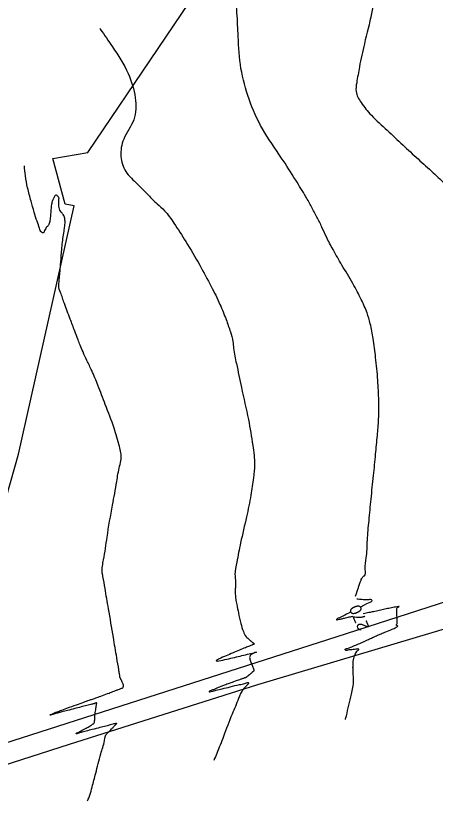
# Model space of a CAD drawing. Extents: x -478464 to -472469, y -1118040 to -1113785.
# Drawn here: x -478027.6 to -477884.4, y -1117519.9 to -1117251.2 of the extents above; entities that cross this region are included whole.
import ezdxf

# ---------------------------------------------------------------- set-up
doc = ezdxf.new("R2010")
doc.units = 0
for name, color, linetype in [('ObPÚ', 7, 'Continuous'), ('silnice', 7, 'Continuous'), ('Vrstevnice_hlavni', 7, 'Continuous'), ('Vrstevnice_popis', 7, 'Continuous'), ('Vrstevnice_vedlejsi', 7, 'Continuous')]:
    doc.layers.add(name, color=color, linetype=linetype)

msp = doc.modelspace()

# ---------------------------------------------------------------- linework, layer by layer
at = {"layer": 'ObPÚ'}
for points in [[(-478036.665, -1117435.774), (-478026.64, -1117400.81), (-478007.71, -1117316.06), (-478010.688, -1117315.457), (-478014.916, -1117299.841), (-478003.02, -1117297.83), (-477955.02, -1117226.727), (-477932.94, -1117194.02), (-477930.86, -1117190.98), (-477927.765, -1117186.164), (-477902.42, -1117146.73), (-477898.94, -1117138.46), (-477889.78, -1117115.18), (-477874.35, -1117091.12), (-477871.53, -1117086.61), (-477868.88, -1117081.98), (-477862.66, -1117057.28), (-477855.79, -1117029.92), (-477851.66, -1117013.57), (-477838.11, -1116918.83), (-477838.17, -1116915.03), (-477838.53, -1116880.06), (-477835.42, -1116846.57)], [(-477192.43, -1117425.62), (-477239.17, -1117423.45), (-477286.2, -1117422.09), (-477330.75, -1117420.42), (-477373.93, -1117418.61), (-477420.9, -1117417.49), (-477422.1, -1117417.56), (-477424.2, -1117417.6), (-477428.82, -1117417.33), (-477494.83, -1117414.18), (-477554.51, -1117411.78), (-477621.5, -1117408.68), (-477644.72, -1117408.28), (-477682.13, -1117413.46), (-477685.93, -1117414.02), (-477688.8, -1117414.36), (-477691.73, -1117414.77), (-477738.55, -1117419.44), (-477782.49, -1117430.5), (-477808.98, -1117437.26), (-477845.5, -1117449.81), (-477945.12, -1117479.46), (-478009.37, -1117499.81), (-478071.71, -1117519.91)]]:
    msp.add_lwpolyline(points, dxfattribs=at)
at = {"layer": 'silnice'}
msp.add_lwpolyline([(-478068.596, -1117511.329), (-477917.95, -1117462.993), (-477779.219, -1117418.245), (-477732.944, -1117407.585), (-477720.808, -1117405.048), (-477704.588, -1117403.835), (-477689.402, -1117401.926), (-477652.852, -1117401.691), (-477590.784, -1117403.37), (-477332.447, -1117414.279), (-477204.956, -1117416.797), (-477142.049, -1117416.797), (-477096.756, -1117410.083), (-477036.34, -1117397.174), (-476978.492, -1117379.033), (-476883.712, -1117344.626), (-476756.221, -1117298.47), (-476633.763, -1117254.832), (-476588.47, -1117242.245), (-476550.726, -1117234.692), (-476503.755, -1117230.496), (-476424.073, -1117228.817), (-476282.324, -1117220.425)], dxfattribs=at)
at = {"layer": 'Vrstevnice_hlavni'}
for points in [[(-477911.583, -1117449.228), (-477910.477, -1117445.772), (-477910.019, -1117444.447), (-477909.658, -1117443.526), (-477909.392, -1117443.009), (-477909.13, -1117442.624), (-477908.873, -1117442.372), (-477908.621, -1117442.252), (-477908.32, -1117440.177), (-477907.97, -1117436.148), (-477907.573, -1117430.164), (-477907.024, -1117423.487), (-477906.324, -1117416.119), (-477905.473, -1117408.06), (-477904.757, -1117400.83), (-477904.178, -1117394.43), (-477903.734, -1117388.86), (-477903.684, -1117382.559), (-477904.026, -1117375.527), (-477904.762, -1117367.764), (-477905.619, -1117361.343), (-477906.598, -1117356.266), (-477907.698, -1117352.532), (-477909.68, -1117347.951), (-477912.544, -1117342.521), (-477916.289, -1117336.243), (-477919.3, -1117330.94), (-477921.576, -1117326.612), (-477923.119, -1117323.257), (-477924.801, -1117319.855), (-477926.621, -1117316.406), (-477928.579, -1117312.91), (-477932.023, -1117307.311), (-477936.953, -1117299.609), (-477943.367, -1117289.805), (-477947.957, -1117279.645), (-477950.723, -1117269.132), (-477951.664, -1117258.263), (-477952.088, -1117250.196), (-477951.996, -1117244.93), (-477951.386, -1117242.465), (-477951.356, -1117240.437), (-477951.906, -1117238.846), (-477954.163, -1117236.539)], [(-477909.977, -1117452.965), (-477906.683, -1117451.282), (-477905.981, -1117450.731), (-477906.225, -1117450.469), (-477907.414, -1117450.497), (-477908.49, -1117450.482), (-477909.453, -1117450.426), (-477911.153, -1117450.228)], [(-477915.078, -1117491.334), (-477914.758, -1117490.096), (-477913.057, -1117482.71), (-477912.276, -1117478.035), (-477912.416, -1117476.071), (-477912.486, -1117474.339), (-477912.485, -1117472.841), (-477912.413, -1117471.575), (-477912.24, -1117470.477), (-477911.965, -1117469.547), (-477911.588, -1117468.784), (-477911.224, -1117468.179), (-477910.875, -1117467.731), (-477910.539, -1117467.441), (-477910.602, -1117467.288), (-477911.064, -1117467.272), (-477911.925, -1117467.394), (-477912.881, -1117467.505), (-477913.932, -1117467.605), (-477915.078, -1117467.696), (-477915.213, -1117467.508), (-477914.336, -1117467.043), (-477912.448, -1117466.301), (-477910.623, -1117465.544), (-477908.86, -1117464.773), (-477907.159, -1117463.989), (-477905.794, -1117463.361), (-477904.767, -1117462.89), (-477904.076, -1117462.575), (-477902.898, -1117462.073), (-477901.234, -1117461.381), (-477899.083, -1117460.501), (-477897.749, -1117459.856), (-477897.231, -1117459.445), (-477897.531, -1117459.27), (-477897.673, -1117459.108), (-477897.657, -1117458.96), (-477897.483, -1117458.826), (-477897.4, -1117458.217), (-477897.409, -1117457.134), (-477897.509, -1117455.576), (-477897.559, -1117454.436), (-477897.557, -1117453.715), (-477897.505, -1117453.413), (-477897.342, -1117453.155), (-477897.069, -1117452.941), (-477896.686, -1117452.773), (-477897.009, -1117452.778), (-477898.037, -1117452.957), (-477899.772, -1117453.31), (-477901.6, -1117453.691), (-477903.52, -1117454.102), (-477905.533, -1117454.541), (-477907.034, -1117454.867), (-477908.024, -1117455.082), (-477908.98, -1117455.286)], [(-477913.191, -1117454.606), (-477915.268, -1117455.667), (-477916.239, -1117456.168), (-477917.145, -1117456.64), (-477917.983, -1117457.083), (-477918.11, -1117457.279), (-477917.524, -1117457.226), (-477916.227, -1117456.926), (-477915.1, -1117456.663), (-477914.142, -1117456.438), (-477912.565, -1117456.061)]]:
    msp.add_spline(points, degree=3, dxfattribs=at)
at = {"layer": 'Vrstevnice_vedlejsi'}
for points in [[(-477804.386, -1117419.488), (-477804.459, -1117419.188), (-477804.433, -1117418.828), (-477804.309, -1117418.408), (-477804.087, -1117417.929), (-477803.934, -1117417.608), (-477803.851, -1117417.446), (-477803.837, -1117417.442), (-477803.822, -1117417.43), (-477803.805, -1117417.41), (-477803.787, -1117417.381), (-477803.78, -1117417.35), (-477803.784, -1117417.318), (-477803.798, -1117417.285), (-477803.846, -1117417.041), (-477803.927, -1117416.587), (-477804.04, -1117415.924), (-477804.155, -1117415.491), (-477804.272, -1117415.29), (-477804.39, -1117415.321), (-477804.727, -1117415.276), (-477805.285, -1117415.155), (-477806.062, -1117414.959), (-477806.661, -1117414.179), (-477807.083, -1117412.816), (-477807.326, -1117410.868), (-477807.929, -1117408.579), (-477808.891, -1117405.947), (-477810.211, -1117402.974), (-477810.939, -1117399.862), (-477811.074, -1117396.614), (-477810.616, -1117393.228), (-477810.756, -1117387.654), (-477811.492, -1117379.894), (-477812.825, -1117369.947), (-477814.001, -1117361.455), (-477815.021, -1117354.417), (-477815.885, -1117348.835), (-477817.217, -1117342.529), (-477819.02, -1117335.501), (-477821.291, -1117327.751), (-477824.632, -1117319.053), (-477829.042, -1117309.407), (-477834.521, -1117298.815), (-477839.072, -1117290.84), (-477842.696, -1117285.481), (-477845.392, -1117282.741), (-477847.121, -1117280.083), (-477847.883, -1117277.508), (-477847.679, -1117275.017), (-477848.818, -1117269.742), (-477851.301, -1117261.684), (-477855.128, -1117250.842), (-477858.13, -1117241.057), (-477860.308, -1117232.328), (-477861.662, -1117224.656), (-477862.366, -1117217.654), (-477862.42, -1117211.323), (-477861.824, -1117205.661), (-477863.512, -1117199.828), (-477867.485, -1117193.824), (-477873.743, -1117187.648), (-477879.164, -1117182.394), (-477883.749, -1117178.064), (-477887.498, -1117174.655), (-477893.02, -1117171.134), (-477900.315, -1117167.498), (-477909.382, -1117163.749), (-477915.572, -1117161.214), (-477918.886, -1117159.892), (-477919.321, -1117159.784), (-477919.639, -1117159.708), (-477919.838, -1117159.664), (-477919.919, -1117159.653), (-477920.013, -1117159.646), (-477920.119, -1117159.642), (-477920.238, -1117159.643), (-477924.722, -1117159.296), (-477933.571, -1117158.602), (-477934.082, -1117158.562)], [(-477954.454, -1117189.777), (-477948.211, -1117191.791), (-477936.422, -1117195.896), (-477928.048, -1117199.17), (-477923.089, -1117201.613), (-477921.545, -1117203.226), (-477918.986, -1117206.68), (-477915.414, -1117211.974), (-477910.828, -1117219.108), (-477907.487, -1117225.392), (-477905.391, -1117230.828), (-477904.539, -1117235.414), (-477904.79, -1117241.921), (-477906.143, -1117250.35), (-477908.597, -1117260.701), (-477910.296, -1117268.595), (-477911.24, -1117274.034), (-477911.429, -1117277.017), (-477909.757, -1117280.714), (-477906.224, -1117285.125), (-477900.83, -1117290.251), (-477895.519, -1117295.224), (-477890.29, -1117300.046), (-477885.145, -1117304.716), (-477880.549, -1117309.008), (-477876.503, -1117312.924), (-477873.006, -1117316.462), (-477870.428, -1117320.233), (-477868.77, -1117324.236), (-477868.031, -1117328.472), (-477866.681, -1117334.328), (-477864.72, -1117341.805), (-477862.147, -1117350.902), (-477860.639, -1117359.029), (-477860.198, -1117366.184), (-477860.823, -1117372.368), (-477861.454, -1117378.874), (-477862.091, -1117385.702), (-477862.734, -1117392.851), (-477863.037, -1117399.446), (-477862.998, -1117405.488), (-477862.617, -1117410.976), (-477862.345, -1117415.865), (-477862.18, -1117420.156), (-477862.122, -1117423.848), (-477862.019, -1117426.978), (-477861.868, -1117429.545), (-477861.672, -1117431.549), (-477861.33, -1117433.074), (-477860.844, -1117434.119), (-477860.213, -1117434.684), (-477859.737, -1117435.119), (-477859.415, -1117435.425), (-477859.249, -1117435.601), (-477859.805, -1117436.002), (-477861.085, -1117436.629), (-477863.088, -1117437.481), (-477864.741, -1117438.177), (-477866.043, -1117438.717), (-477866.996, -1117439.1), (-477868.438, -1117439.714), (-477870.371, -1117440.557), (-477872.793, -1117441.629), (-477874.666, -1117442.446), (-477875.99, -1117443.008), (-477876.763, -1117443.314), (-477877.55, -1117443.633), (-477878.351, -1117443.965), (-477879.164, -1117444.31), (-477879.357, -1117444.451), (-477878.928, -1117444.387), (-477877.878, -1117444.12), (-477877.052, -1117443.907), (-477876.449, -1117443.747), (-477876.07, -1117443.642), (-477874.783, -1117443.296), (-477872.588, -1117442.71)], [(-477998.879, -1117255.557), (-477998.727, -1117255.77), (-477994.613, -1117261.766), (-477989.226, -1117270.883), (-477986.788, -1117279.171), (-477987.299, -1117286.631), (-477990.759, -1117293.261), (-477991.682, -1117299.15), (-477990.068, -1117304.296), (-477985.915, -1117308.701), (-477982.328, -1117312.403), (-477979.306, -1117315.404), (-477976.849, -1117317.702), (-477973.612, -1117321.957), (-477969.594, -1117328.168), (-477964.797, -1117336.336), (-477960.899, -1117343.504), (-477957.9, -1117349.67), (-477955.8, -1117354.835), (-477954.323, -1117359.055), (-477953.469, -1117362.331), (-477953.239, -1117364.661), (-477952.282, -1117369.883), (-477950.598, -1117377.995), (-477948.188, -1117388.997), (-477946.693, -1117397.801), (-477946.113, -1117404.405), (-477946.449, -1117408.81), (-477947.352, -1117414.723), (-477948.823, -1117422.144), (-477950.861, -1117431.072), (-477952.177, -1117437.645), (-477952.771, -1117441.863), (-477952.644, -1117443.726), (-477952.589, -1117445.223), (-477952.606, -1117446.354), (-477952.696, -1117447.119), (-477952.711, -1117448.007), (-477952.649, -1117449.018), (-477952.512, -1117450.153), (-477952.156, -1117452.114), (-477951.583, -1117454.901), (-477950.791, -1117458.515), (-477949.91, -1117461.246), (-477948.939, -1117463.094), (-477947.878, -1117464.059), (-477947.136, -1117464.728), (-477946.712, -1117465.101), (-477946.606, -1117465.179), (-477946.495, -1117465.26), (-477946.379, -1117465.346), (-477946.257, -1117465.436), (-477946.233, -1117465.524), (-477946.307, -1117465.609), (-477946.478, -1117465.691), (-477946.651, -1117465.772), (-477946.824, -1117465.851), (-477946.999, -1117465.928), (-477947.792, -1117466.25), (-477949.203, -1117466.816), (-477951.232, -1117467.627), (-477953.439, -1117468.556), (-477955.824, -1117469.604), (-477958.387, -1117470.771), (-477959.194, -1117471.349), (-477958.243, -1117471.339)], [(-477991.867, -1117477.245), (-477991.928, -1117477.172), (-477992.04, -1117476.677), (-477992.202, -1117475.763), (-477992.413, -1117474.428), (-477993.107, -1117470.277), (-477994.282, -1117463.311), (-477995.94, -1117453.528), (-477997.123, -1117446.591), (-477997.83, -1117442.497), (-477998.062, -1117441.249), (-477997.593, -1117436.785), (-477996.423, -1117429.106), (-477994.553, -1117418.212), (-477993.126, -1117410.136), (-477992.143, -1117404.879), (-477991.604, -1117402.439), (-477992.237, -1117398.118), (-477994.043, -1117391.915), (-477997.021, -1117383.831), (-477999.558, -1117377.283), (-478001.654, -1117372.273), (-478003.307, -1117368.799), (-478004.636, -1117365.887), (-478005.64, -1117363.535), (-478006.319, -1117361.745), (-478007.439, -1117358.786), (-478009, -1117354.657), (-478011.003, -1117349.359), (-478012.316, -1117345.574), (-478012.939, -1117343.304), (-478012.872, -1117342.547), (-478012.777, -1117341.561), (-478012.655, -1117340.344), (-478012.505, -1117338.897), (-478012.348, -1117337.07), (-478012.182, -1117334.863), (-478012.009, -1117332.276), (-478011.775, -1117329.718), (-478011.478, -1117327.189), (-478011.12, -1117324.688), (-478010.876, -1117322.931), (-478010.745, -1117321.917), (-478010.728, -1117321.646), (-478010.753, -1117321.243), (-478010.821, -1117320.708), (-478010.93, -1117320.041), (-478011.029, -1117319.606), (-478011.115, -1117319.402), (-478011.19, -1117319.431), (-478011.241, -1117319.41), (-478011.268, -1117319.341), (-478011.271, -1117319.224), (-478011.447, -1117318.941), (-478011.795, -1117318.493), (-478012.316, -1117317.879), (-478012.672, -1117317.097), (-478012.863, -1117316.147), (-478012.89, -1117315.028), (-478012.892, -1117314.215), (-478012.869, -1117313.71), (-478012.821, -1117313.512), (-478012.909, -1117313.243), (-478013.131, -1117312.902), (-478013.489, -1117312.491), (-478013.809, -1117312.342), (-478014.093, -1117312.455), (-478014.34, -1117312.83), (-478014.581, -1117313.247), (-478014.817, -1117313.705), (-478015.046, -1117314.206), (-478015.238, -1117314.822), (-478015.392, -1117315.554), (-478015.508, -1117316.401), (-478015.602, -1117317.301), (-478015.672, -1117318.253), (-478015.72, -1117319.257), (-478015.808, -1117320.173), (-478015.935, -1117321.003), (-478016.103, -1117321.746), (-478016.33, -1117322.362), (-478016.618, -1117322.853), (-478016.967, -1117323.218), (-478017.343, -1117323.742), (-478017.748, -1117324.426), (-478018.182, -1117325.269), (-478018.755, -1117325.029), (-478019.468, -1117323.706), (-478020.32, -1117321.3), (-478021.282, -1117318.195), (-478022.355, -1117314.389), (-478023.538, -1117309.884), (-478024.297, -1117305.737), (-478024.625, -1117302.334)], [(-477958.243, -1117471.339), (-477955.536, -1117470.741), (-477952.915, -1117470.142), (-477950.378, -1117469.541), (-477947.927, -1117468.939), (-477946.283, -1117468.538), (-477945.445, -1117468.338), (-477945.414, -1117468.339), (-477945.712, -1117468.473), (-477946.339, -1117468.742), (-477947.296, -1117469.144), (-477947.728, -1117469.923), (-477947.635, -1117471.079), (-477947.017, -1117472.611), (-477946.597, -1117473.709), (-477946.375, -1117474.371), (-477946.35, -1117474.598), (-477946.374, -1117474.773), (-477946.445, -1117474.897), (-477946.564, -1117474.97), (-477946.676, -1117475.037), (-477946.782, -1117475.1), (-477946.881, -1117475.157), (-477946.943, -1117475.205), (-477946.968, -1117475.243), (-477946.957, -1117475.27), (-477947.157, -1117475.466), (-477947.57, -1117475.831), (-477948.194, -1117476.365), (-477948.672, -1117476.747), (-477949.004, -1117476.976), (-477949.191, -1117477.054), (-477949.465, -1117477.156), (-477949.826, -1117477.283), (-477950.274, -1117477.435), (-477951.24, -1117477.772), (-477952.723, -1117478.294), (-477954.724, -1117479.003), (-477956.35, -1117479.597), (-477957.602, -1117480.076), (-477958.479, -1117480.441), (-477959.413, -1117480.834), (-477960.402, -1117481.255), (-477961.448, -1117481.704), (-477961.603, -1117481.871), (-477960.869, -1117481.757), (-477959.244, -1117481.361), (-477957.105, -1117480.843), (-477954.45, -1117480.202), (-477951.281, -1117479.438), (-477949.178, -1117478.982), (-477948.142, -1117478.834), (-477948.174, -1117478.994), (-477948.491, -1117479.411), (-477949.094, -1117480.085), (-477949.982, -1117481.016), (-477951.543, -1117484.163), (-477953.776, -1117489.526), (-477956.682, -1117497.105), (-477959.001, -1117502.97), (-477959.941, -1117505.268)], [(-478003.144, -1117519.112), (-478003.132, -1117519.091), (-478002.849, -1117518.531), (-478002.564, -1117517.866), (-478002.277, -1117517.095), (-478001.519, -1117514.373), (-478000.289, -1117509.7), (-477998.587, -1117503.075), (-477997.307, -1117498.528), (-477996.448, -1117496.058), (-477996.011, -1117495.664), (-477995.494, -1117495.164), (-477994.897, -1117494.557), (-477994.22, -1117493.842), (-477993.709, -1117493.305), (-477993.364, -1117492.946), (-477993.185, -1117492.764), (-477993.124, -1117492.659), (-477993.181, -1117492.63), (-477993.356, -1117492.676), (-477993.771, -1117492.785), (-477994.426, -1117492.954), (-477995.322, -1117493.185), (-477996.795, -1117493.562), (-477998.846, -1117494.085), (-478001.473, -1117494.753), (-478003.611, -1117495.312), (-478005.26, -1117495.76), (-478006.419, -1117496.098), (-478006.996, -1117496.219), (-478006.993, -1117496.123), (-478006.408, -1117495.809), (-478005.709, -1117495.438), (-478004.894, -1117495.01), (-478003.965, -1117494.524), (-478003.169, -1117494.089), (-478002.505, -1117493.706), (-478001.974, -1117493.373), (-478001.536, -1117493.087), (-478001.191, -1117492.847), (-478000.937, -1117492.652), (-478000.751, -1117492.194), (-478000.632, -1117491.473), (-478000.581, -1117490.488), (-478000.498, -1117489.492), (-478000.385, -1117488.485), (-478000.24, -1117487.467), (-478000.128, -1117486.703), (-478000.048, -1117486.194), (-478000.001, -1117485.94), (-477999.965, -1117485.766), (-477999.941, -1117485.673), (-477999.928, -1117485.661), (-478000.489, -1117485.799), (-478001.623, -1117486.089), (-478003.33, -1117486.529), (-478005.282, -1117487.037), (-478007.479, -1117487.611), (-478009.922, -1117488.252), (-478011.864, -1117488.767), (-478013.305, -1117489.157), (-478014.246, -1117489.421), (-478014.977, -1117489.616), (-478015.498, -1117489.744), (-478015.809, -1117489.803), (-478015.836, -1117489.758), (-478015.578, -1117489.608), (-478015.036, -1117489.355), (-478014.549, -1117489.136), (-478014.118, -1117488.952), (-478013.741, -1117488.803), (-478012.405, -1117488.306), (-478010.108, -1117487.462), (-478006.85, -1117486.27), (-478004.315, -1117485.357), (-478002.502, -1117484.722), (-478001.412, -1117484.367), (-477999.922, -1117483.843), (-477998.032, -1117483.15), (-477995.742, -1117482.288), (-477994.054, -1117481.654), (-477992.967, -1117481.248), (-477992.483, -1117481.068), (-477991.998, -1117480.879), (-477991.512, -1117480.68), (-477991.026, -1117480.472), (-477990.843, -1117480.006), (-477990.962, -1117479.282), (-477991.383, -1117478.3), (-477991.685, -1117477.622), (-477991.867, -1117477.245)]]:
    msp.add_spline(points, degree=3, dxfattribs=at)

# ---------------------------------------------------------------- texts
at = {"layer": 'Vrstevnice_popis'}
msp.add_text(' 270 ', height=4, rotation=113.25113, dxfattribs=at).set_placement((-477906.182, -1117461.291))

doc.saveas('drawing.dxf')
